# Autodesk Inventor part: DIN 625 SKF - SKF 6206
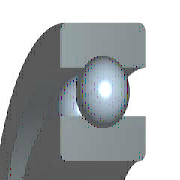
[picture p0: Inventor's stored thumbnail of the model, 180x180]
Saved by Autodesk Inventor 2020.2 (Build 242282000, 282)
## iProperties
Manager: www.cadconsulting.pl
Company: Fabian Stasiak CAD Consulting
Created: 2010-02
Part Number: DIN 625 SKF - SKF 6206
Material: Stal, miękka
Description: Łożyska kulkowe jednorzędowe
Document SubType Name: Modeling
Standard: DIN 625
Designer: F.Stasiak
Standards Organization: DIN
Language: pl-PL
Size Designation: SKF 6206
Categories: <MemberInstance><Categories><Category DisplayName="Części wałów" InternalName="7f7aeb1f-a693-4053-b835-cee3144e0d98" Mnemonic="SHFT"><Category DisplayName="Łoży
Density: 7.86 g/cm^3
Appearance: Metal-Stal
IsCustomPart: 0
Author: F.Stasiak
Subject: Zbiór ćwiczeń. Autodesk Inventor 2020. Kurs podstawowy
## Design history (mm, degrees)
node "Sketch1"
node "WorkPoint1"
sketch "Sketch2"
  geometry: L1 (15, 16)-(31, 16); L2 (15, 0)-(15, 16); L3 (31, 0)-(15, 0); L4 (31, 16)-(31, 0); L5 (0, 0)-(0, 20); L6 (0, 0)-(0, 20); L7 (-7.2, 0)-(43.2, 0) reference
  constraints: 12 end point, 3 vertical, 2 horizontal, 1 collinear, 1 other
  dimensions: "d1" = 30 diameter of L1.start L5 (= Diam); "d3" = 62 diameter of L1.end L5 (= DD); "d5" = 16 distance of L2.start L1.start (= msp_mdtd2)
revolve "Revolution1" sketch "Sketch2" stored, may be unused: angle "d6" = 360 deg
node "WorkAxis1"
node "WorkPlane3"
sketch "Sketch3"
  geometry: L1 (25.88, 16)-(25.88, 11.84); L2 (20.12, 16)-(25.88, 16); L3 (20.12, 11.84)-(20.12, 16); L4 (20.12, 0)-(20.12, 4.16); L5 (25.88, 0)-(20.12, 0); L6 (25.88, 4.16)-(25.88, 0); L7 (31, 0)-(-31, 0) reference; L8 (31, 16)-(-31, 16) reference; L9 (0, -42.29)-(0, 61.29); L10 (0, 82.007)-(0, -63.007) reference; A1 r 4.8 centre (23, 8) between (25.88, 4.16) and (25.88, 11.84); A2 r 4.8 centre (23, 8) between (20.12, 11.84) and (20.12, 4.16)
  constraints: 14 end point, 4 collinear, 4 point on circle, 4 vertical, 2 centre point, 2 concentric, 2 horizontal, 2 point on line
  dimensions: "d9" = 9.6 diameter of A1 (= msp_mdtd6); "d21" = 20.12 distance between parallel lines of L9 L4 (= 0.5 x msp_d1); "d22" = 23 distance from line of L9 A1.centre (= 0.5 x msp_ds); "d23" = 25.88 distance between parallel lines of L9 L6 (= 0.5 x msp_dd1)
revolve "Revolution2" sketch "Sketch3" stored, may be unused: angle "d10" = 360 deg
node "WorkPlane4"
node "Sketch4"
node "WorkPoint2"
revolve "Revolution3" stored, may be unused: angle "d16" = 360 deg
pattern_circular "PolarArray1" dims "d17" = 75.875 (= msp_pocet), angle "d19" = 360 deg
fillet "Fillet1" dims "d20" = 1 (= r)
body "Solid1"
sketch "Sketch5"
  geometry: L1 (23, 3.2)-(23, 12.8); L2 (25.88, 0)-(-25.88, 0) reference; L3 (23, 3.2)-(23, 12.8); A1 r 4.8 centre (23, 8) between (23, 3.2) and (23, 12.8); A2 r 4.8 centre (23, 8) between (25.88, 4.16) and (25.88, 11.84) reference
  constraints: 4 end point, 2 point on circle, 1 centre point, 1 concentric, 1 vertical
  dimensions: "d13" = 0 horizontal distance of A1.centre L1.start; "d15" = 9.6001 diameter of A1 (computed from msp_mdtd6)
other parameters: "Diam" = 30 [user parameter; used in 3 equation terms], "DD" = 62 [user parameter; used in 3 equation terms], "B" = 16 [user parameter; used in 1 equation term], "r" = 1 [user parameter; used in 1 equation term], "msp_ds" = 46 (= 0.5 x Diam + 0.5 x DD) [user parameter; used in 5 equation terms], "msp_d0" = 9.6 (= -0.3 x Diam + 0.3 x DD) [user parameter; used in 4 equation terms], "msp_d1" = 40.24 (= msp_ds - 0.6 x msp_d0) [user parameter; used in 1 equation term], "msp_dd1" = 51.76 (= msp_ds + 0.6 x msp_d0) [user parameter; used in 1 equation term], "msp_pom" = 69 (= 1.5 x msp_ds) [user parameter; used in 1 equation term], "msp_mdtd2" = 16 (= B) [user parameter; used in 3 equation terms], "msp_mdtd4" = 46 (= msp_ds) [user parameter], "msp_mdtd6" = 9.6 (= msp_d0) [user parameter; used in 2 equation terms], "msp_mdtd7" = 8 (= 0.5 x msp_mdtd2) [user parameter], "msp_pocet" = 75.875 (computed from msp_d0, msp_pom) [user parameter; used in 1 equation term], "d2" = 72 (derived), "d4" = 19 (derived), "d7" = 0, "d8" = 15.6 (derived), "d11" = -16 (computed from msp_mdtd2), "d12" = 0 (derived), "d14" = 15.6001 (derived), "d26" = 0, "d27" = 0, "d28" = 0, "d29" = 0, "d30" = 0
